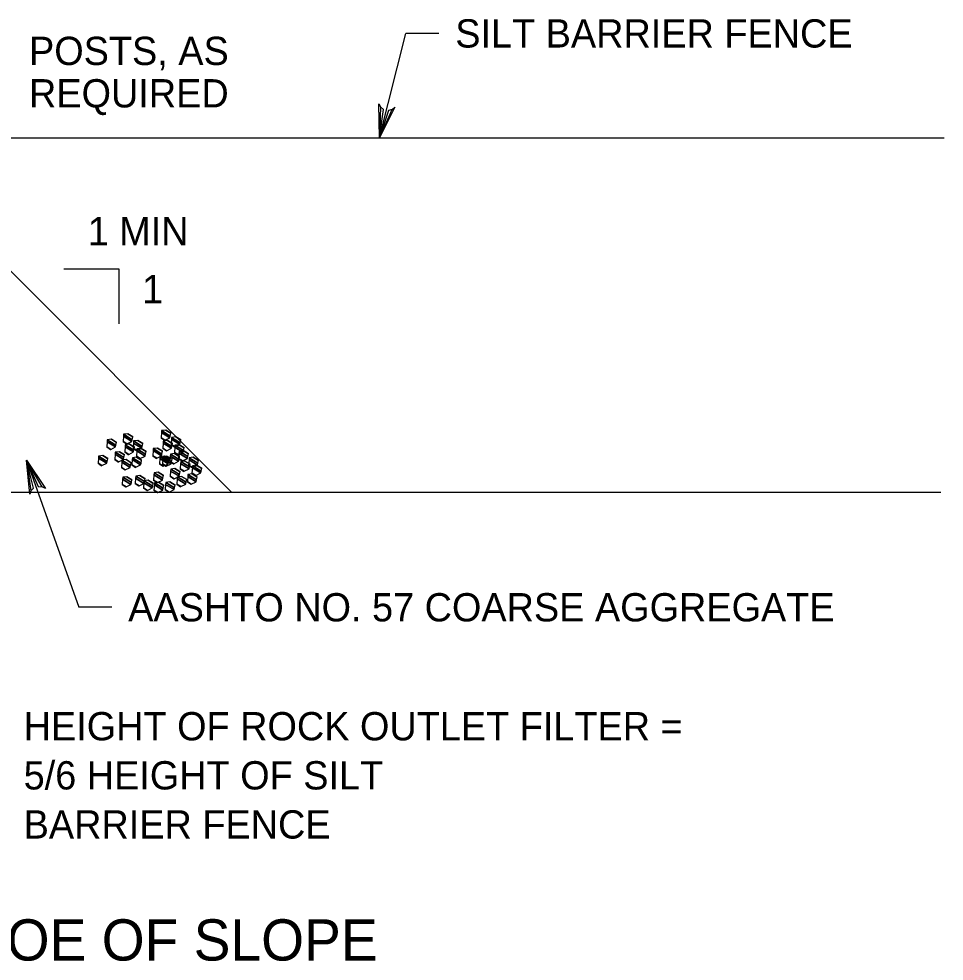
# Model space of a CAD drawing. Extents: x 636462 to 639049, y 299944 to 300538.
# Drawn here: x 637772.2 to 637870.3, y 300114 to 300213.9 of the extents above; entities that cross this region are included whole.
import ezdxf

# ---------------------------------------------------------------- set-up
doc = ezdxf.new("R2010")
doc.units = 0
doc.layers.add('Default', color=7, linetype='Continuous')

msp = doc.modelspace()

# ---------------------------------------------------------------- linework, layer by layer
at = {"layer": 'Default'}
for p, q in [((637810.476, 300201.292), (637813.243, 300212.352)), ((637816.741, 300212.352), (637813.243, 300212.352)), ((637761.425, 300201.292), (637870.293, 300201.292)), ((637794.794, 300163.723), (637763.334, 300195.182)), ((637773.044, 300167.11), (637778.583, 300151.525)), ((637719.268, 300163.723), (637869.927, 300163.723)), ((637782.081, 300151.525), (637778.583, 300151.525))]:
    msp.add_line(p, q, dxfattribs=at)
for points in [[(637811.811, 300204.304), (637812.088, 300204.517), (637810.476, 300201.292), (637811.811, 300204.304), (637811.404, 300204.195), (637810.476, 300201.292), (637810.892, 300204.304), (637810.566, 300204.565), (637810.476, 300201.292), (637810.381, 300204.896), (637810.566, 300204.565)], [(637777.012, 300187.412), (637782.853, 300187.412), (637782.853, 300181.575)], [(637773.525, 300163.851), (637773.405, 300163.523), (637773.044, 300167.11), (637773.525, 300163.851), (637773.811, 300164.161), (637773.044, 300167.11), (637774.302, 300164.342), (637774.717, 300164.296), (637773.044, 300167.11), (637775.051, 300164.115), (637774.717, 300164.296)]]:
    msp.add_lwpolyline(points, dxfattribs=at)
for points in [[(637787.369, 300170.247), (637788.288, 300169.677), (637788.352, 300169.966), (637787.81, 300170.302)], [(637787.81, 300170.302), (637788.352, 300169.966), (637788.354, 300169.974), (637788.354, 300169.974)], [(637781.603, 300169.07), (637782.491, 300168.52), (637782.537, 300168.718), (637781.619, 300169.286)], [(637781.619, 300169.286), (637782.537, 300168.718), (637782.602, 300168.997), (637782.056, 300169.335)], [(637782.056, 300169.335), (637782.602, 300168.997), (637782.604, 300169.007), (637782.604, 300169.007)], [(637783.284, 300169.092), (637783.703, 300168.832), (637784.22, 300169.092), (637783.325, 300169.647)], [(637783.325, 300169.647), (637784.22, 300169.092), (637784.263, 300169.285), (637783.34, 300169.857)], [(637783.34, 300169.857), (637784.263, 300169.285), (637784.327, 300169.575), (637783.781, 300169.913)], [(637783.781, 300169.913), (637784.327, 300169.575), (637784.329, 300169.586), (637784.329, 300169.586)], [(637787.313, 300169.481), (637787.727, 300169.224), (637788.245, 300169.481), (637787.353, 300170.033)], [(637787.699, 300169.21), (637787.699, 300169.21), (637787.727, 300169.224), (637787.313, 300169.481)], [(637787.353, 300170.033), (637788.245, 300169.481), (637788.288, 300169.677), (637787.369, 300170.247)], [(637788.378, 300168.773), (637788.795, 300168.515), (637789.309, 300168.773), (637788.416, 300169.326)], [(637788.416, 300169.326), (637789.309, 300168.773), (637789.352, 300168.966), (637788.431, 300169.537)], [(637788.431, 300169.537), (637789.352, 300168.966), (637789.417, 300169.25), (637788.866, 300169.592)], [(637788.866, 300169.592), (637789.417, 300169.25), (637789.42, 300169.264), (637789.42, 300169.264)], [(637781.563, 300168.52), (637781.981, 300168.26), (637782.491, 300168.52), (637781.603, 300169.07)], [(637781.947, 300168.243), (637781.947, 300168.243), (637781.981, 300168.26), (637781.563, 300168.52)], [(637783.67, 300168.815), (637783.67, 300168.815), (637783.703, 300168.832), (637783.284, 300169.092)], [(637783.466, 300167.988), (637783.884, 300167.729), (637784.398, 300167.988), (637783.502, 300168.543)], [(637783.502, 300168.543), (637784.398, 300167.988), (637784.441, 300168.179), (637783.516, 300168.753)], [(637783.516, 300168.753), (637784.441, 300168.179), (637784.505, 300168.469), (637783.957, 300168.809)], [(637783.957, 300168.809), (637784.505, 300168.469), (637784.507, 300168.48), (637784.507, 300168.48)], [(637784.35, 300168.384), (637784.765, 300168.127), (637785.28, 300168.384), (637784.39, 300168.936)], [(637784.734, 300168.111), (637784.734, 300168.111), (637784.765, 300168.127), (637784.35, 300168.384)], [(637784.39, 300168.936), (637785.28, 300168.384), (637785.324, 300168.582), (637784.406, 300169.151)], [(637784.406, 300169.151), (637785.324, 300168.582), (637785.389, 300168.872), (637784.845, 300169.21)], [(637784.742, 300168.094), (637785.634, 300167.541), (637785.678, 300167.741), (637784.758, 300168.312)], [(637784.758, 300168.312), (637785.678, 300167.741), (637785.741, 300168.03), (637785.199, 300168.366)], [(637784.845, 300169.21), (637785.389, 300168.872), (637785.391, 300168.88), (637785.391, 300168.88)], [(637785.199, 300168.366), (637785.741, 300168.03), (637785.743, 300168.039), (637785.743, 300168.039)], [(637786.469, 300168.13), (637787.361, 300167.577), (637787.405, 300167.771), (637786.483, 300168.342)], [(637786.483, 300168.342), (637787.405, 300167.771), (637787.469, 300168.058), (637786.92, 300168.399)], [(637786.92, 300168.399), (637787.469, 300168.058), (637787.472, 300168.071), (637787.472, 300168.071)], [(637787.49, 300168.374), (637787.903, 300168.118), (637788.423, 300168.374), (637787.53, 300168.928)], [(637787.873, 300168.103), (637787.873, 300168.103), (637787.903, 300168.118), (637787.49, 300168.374)], [(637787.53, 300168.928), (637788.423, 300168.374), (637788.466, 300168.57), (637787.545, 300169.141)], [(637787.545, 300169.141), (637788.466, 300168.57), (637788.53, 300168.858), (637787.986, 300169.195)], [(637787.986, 300169.195), (637788.53, 300168.858), (637788.532, 300168.87), (637788.532, 300168.87)], [(637788.757, 300168.496), (637788.757, 300168.496), (637788.795, 300168.515), (637788.378, 300168.773)], [(637788.73, 300167.935), (637789.152, 300167.674), (637789.661, 300167.935), (637788.771, 300168.487)], [(637788.771, 300168.487), (637789.661, 300167.935), (637789.705, 300168.131), (637788.787, 300168.7)], [(637788.787, 300168.7), (637789.705, 300168.131), (637789.77, 300168.414), (637789.224, 300168.753)], [(637789.224, 300168.753), (637789.77, 300168.414), (637789.772, 300168.423), (637789.772, 300168.423)], [(637780.634, 300166.793), (637781.05, 300166.535), (637781.563, 300166.793), (637780.674, 300167.344)], [(637780.674, 300167.344), (637781.563, 300166.793), (637781.608, 300166.99), (637780.689, 300167.559)], [(637780.689, 300167.559), (637781.608, 300166.99), (637781.673, 300167.274), (637781.126, 300167.614)], [(637781.126, 300167.614), (637781.673, 300167.274), (637781.676, 300167.286), (637781.676, 300167.286)], [(637782.404, 300167.189), (637782.818, 300166.933), (637783.332, 300167.189), (637782.443, 300167.741)], [(637782.443, 300167.741), (637783.332, 300167.189), (637783.377, 300167.39), (637782.459, 300167.96)], [(637782.459, 300167.96), (637783.377, 300167.39), (637783.441, 300167.676), (637782.895, 300168.014)], [(637782.895, 300168.014), (637783.441, 300167.676), (637783.444, 300167.687), (637783.444, 300167.687)], [(637783.844, 300167.709), (637783.844, 300167.709), (637783.884, 300167.729), (637783.466, 300167.988)], [(637784.254, 300167.173), (637785.15, 300166.617), (637785.193, 300166.808), (637784.269, 300167.381)], [(637784.269, 300167.381), (637785.193, 300166.808), (637785.257, 300167.1), (637784.712, 300167.438)], [(637784.701, 300167.541), (637785.116, 300167.284), (637785.634, 300167.541), (637784.742, 300168.094)], [(637785.088, 300167.27), (637785.088, 300167.27), (637785.116, 300167.284), (637784.701, 300167.541)], [(637784.712, 300167.438), (637785.257, 300167.1), (637785.26, 300167.11), (637785.26, 300167.11)], [(637786.433, 300167.577), (637786.848, 300167.32), (637787.361, 300167.577), (637786.469, 300168.13)], [(637786.813, 300167.302), (637786.813, 300167.302), (637786.848, 300167.32), (637786.433, 300167.577)], [(637787.137, 300166.738), (637787.55, 300166.482), (637788.067, 300166.738), (637787.177, 300167.29)], [(637787.177, 300167.29), (637788.067, 300166.738), (637788.112, 300166.933), (637787.193, 300167.503)], [(637787.193, 300167.503), (637788.112, 300166.933), (637788.178, 300167.222), (637787.634, 300167.559)], [(637787.448, 300166.738), (637787.86, 300166.483), (637788.378, 300166.738), (637787.487, 300167.291)], [(637787.487, 300167.291), (637788.378, 300166.738), (637788.422, 300166.932), (637787.503, 300167.503)], [(637787.503, 300167.503), (637788.422, 300166.932), (637788.487, 300167.219), (637787.937, 300167.559)], [(637787.634, 300167.559), (637788.178, 300167.222), (637788.18, 300167.23), (637788.18, 300167.23)], [(637787.937, 300167.559), (637788.487, 300167.219), (637788.49, 300167.23), (637788.49, 300167.23)], [(637788.243, 300167.005), (637788.661, 300166.746), (637789.175, 300167.005), (637788.282, 300167.559)], [(637788.282, 300167.559), (637789.175, 300167.005), (637789.219, 300167.199), (637788.297, 300167.77)], [(637788.297, 300167.77), (637789.219, 300167.199), (637789.283, 300167.487), (637788.738, 300167.824)], [(637789.117, 300167.656), (637789.117, 300167.656), (637789.152, 300167.674), (637788.73, 300167.935)], [(637788.738, 300167.824), (637789.283, 300167.487), (637789.284, 300167.493), (637789.284, 300167.493)], [(637789.171, 300167.311), (637789.587, 300167.053), (637790.104, 300167.311), (637789.212, 300167.863)], [(637789.555, 300167.037), (637789.555, 300167.037), (637789.587, 300167.053), (637789.171, 300167.311)], [(637789.212, 300167.863), (637790.104, 300167.311), (637790.147, 300167.509), (637789.228, 300168.079)], [(637789.228, 300168.079), (637790.147, 300167.509), (637790.211, 300167.796), (637789.667, 300168.134)], [(637789.667, 300168.134), (637790.211, 300167.796), (637790.213, 300167.806), (637790.213, 300167.806)], [(637790.276, 300167.156), (637791.165, 300166.605), (637791.211, 300166.805), (637790.292, 300167.375)], [(637790.292, 300167.375), (637791.211, 300166.805), (637791.276, 300167.088), (637790.724, 300167.43)], [(637790.724, 300167.43), (637791.276, 300167.088), (637791.279, 300167.098), (637791.279, 300167.098)], [(637781.017, 300166.518), (637781.017, 300166.518), (637781.05, 300166.535), (637780.634, 300166.793)], [(637782.788, 300166.918), (637782.788, 300166.918), (637782.818, 300166.933), (637782.404, 300167.189)], [(637783.11, 300166.35), (637783.524, 300166.093), (637784.044, 300166.35), (637783.149, 300166.905)], [(637783.492, 300166.077), (637783.492, 300166.077), (637783.524, 300166.093), (637783.11, 300166.35)], [(637783.149, 300166.905), (637784.044, 300166.35), (637784.086, 300166.545), (637783.164, 300167.116)], [(637783.164, 300167.116), (637784.086, 300166.545), (637784.149, 300166.836), (637783.605, 300167.173)], [(637783.605, 300167.173), (637784.149, 300166.836), (637784.151, 300166.845), (637784.151, 300166.845)], [(637784.214, 300166.617), (637784.632, 300166.358), (637785.15, 300166.617), (637784.254, 300167.173)], [(637784.596, 300166.34), (637784.596, 300166.34), (637784.632, 300166.358), (637784.214, 300166.617)], [(637787.521, 300166.467), (637787.521, 300166.467), (637787.55, 300166.482), (637787.137, 300166.738)], [(637787.828, 300166.467), (637787.828, 300166.467), (637787.86, 300166.483), (637787.448, 300166.738)], [(637788.625, 300166.728), (637788.625, 300166.728), (637788.661, 300166.746), (637788.243, 300167.005)], [(637789.347, 300166.204), (637789.762, 300165.947), (637790.28, 300166.204), (637789.386, 300166.758)], [(637789.386, 300166.758), (637790.28, 300166.204), (637790.323, 300166.403), (637789.402, 300166.975)], [(637789.402, 300166.975), (637790.323, 300166.403), (637790.387, 300166.693), (637789.845, 300167.029)], [(637789.845, 300167.029), (637790.387, 300166.693), (637790.389, 300166.702), (637790.389, 300166.702)], [(637790.237, 300166.605), (637790.648, 300166.35), (637791.165, 300166.605), (637790.276, 300167.156)], [(637790.615, 300166.334), (637790.615, 300166.334), (637790.648, 300166.35), (637790.237, 300166.605)], [(637790.589, 300165.765), (637791.006, 300165.507), (637791.519, 300165.765), (637790.63, 300166.317)], [(637790.63, 300166.317), (637791.519, 300165.765), (637791.564, 300165.963), (637790.646, 300166.532)], [(637790.646, 300166.532), (637791.564, 300165.963), (637791.628, 300166.249), (637791.08, 300166.588)], [(637791.08, 300166.588), (637791.628, 300166.249), (637791.631, 300166.261), (637791.631, 300166.261)], [(637783.229, 300165.102), (637784.123, 300164.548), (637784.166, 300164.745), (637783.245, 300165.316)], [(637783.245, 300165.316), (637784.166, 300164.745), (637784.228, 300165.027), (637783.68, 300165.367)], [(637783.68, 300165.367), (637784.228, 300165.027), (637784.23, 300165.039), (637784.23, 300165.039)], [(637784.61, 300165.212), (637785.502, 300164.659), (637785.547, 300164.856), (637784.625, 300165.428)], [(637784.625, 300165.428), (637785.547, 300164.856), (637785.613, 300165.144), (637785.064, 300165.484)], [(637785.064, 300165.484), (637785.613, 300165.144), (637785.616, 300165.157), (637785.616, 300165.157)], [(637786.52, 300165.011), (637786.933, 300164.755), (637787.448, 300165.011), (637786.557, 300165.563)], [(637786.557, 300165.563), (637787.448, 300165.011), (637787.493, 300165.209), (637786.572, 300165.779)], [(637786.572, 300165.779), (637787.493, 300165.209), (637787.558, 300165.496), (637787.009, 300165.836)], [(637787.009, 300165.836), (637787.558, 300165.496), (637787.561, 300165.508), (637787.561, 300165.508)], [(637788.291, 300165.411), (637788.705, 300165.155), (637789.218, 300165.411), (637788.328, 300165.963)], [(637788.672, 300165.138), (637788.672, 300165.138), (637788.705, 300165.155), (637788.291, 300165.411)], [(637788.328, 300165.963), (637789.218, 300165.411), (637789.264, 300165.609), (637788.342, 300166.18)], [(637788.342, 300166.18), (637789.264, 300165.609), (637789.329, 300165.889), (637788.779, 300166.231)], [(637788.779, 300166.231), (637789.329, 300165.889), (637789.333, 300165.907), (637789.333, 300165.907)], [(637789.035, 300165.126), (637789.928, 300164.572), (637789.971, 300164.77), (637789.05, 300165.341)], [(637789.05, 300165.341), (637789.971, 300164.77), (637790.035, 300165.061), (637789.493, 300165.397)], [(637789.733, 300165.933), (637789.733, 300165.933), (637789.762, 300165.947), (637789.347, 300166.204)], [(637789.493, 300165.397), (637790.035, 300165.061), (637790.037, 300165.07), (637790.037, 300165.07)], [(637790.102, 300164.835), (637790.515, 300164.579), (637791.032, 300164.835), (637790.142, 300165.387)], [(637790.142, 300165.387), (637791.032, 300164.835), (637791.076, 300165.036), (637790.158, 300165.606)], [(637790.158, 300165.606), (637791.076, 300165.036), (637791.14, 300165.324), (637790.597, 300165.66)], [(637790.973, 300165.49), (637790.973, 300165.49), (637791.006, 300165.507), (637790.589, 300165.765)], [(637790.597, 300165.66), (637791.14, 300165.324), (637791.141, 300165.331), (637791.141, 300165.331)], [(637783.189, 300164.548), (637783.604, 300164.29), (637784.123, 300164.548), (637783.229, 300165.102)], [(637783.573, 300164.275), (637783.573, 300164.275), (637783.604, 300164.29), (637783.189, 300164.548)], [(637784.572, 300164.659), (637784.987, 300164.402), (637785.502, 300164.659), (637784.61, 300165.212)], [(637784.956, 300164.386), (637784.956, 300164.386), (637784.987, 300164.402), (637784.572, 300164.659)], [(637785.456, 300164.176), (637785.875, 300163.916), (637786.386, 300164.176), (637785.497, 300164.727)], [(637785.497, 300164.727), (637786.386, 300164.176), (637786.43, 300164.371), (637785.513, 300164.94)], [(637785.513, 300164.94), (637786.43, 300164.371), (637786.494, 300164.66), (637785.951, 300164.997)], [(637785.951, 300164.997), (637786.494, 300164.66), (637786.495, 300164.665), (637786.495, 300164.665)], [(637786.9, 300164.738), (637786.9, 300164.738), (637786.933, 300164.755), (637786.52, 300165.011)], [(637786.56, 300163.955), (637786.977, 300163.697), (637787.493, 300163.955), (637786.601, 300164.508)], [(637786.601, 300164.508), (637787.493, 300163.955), (637787.536, 300164.15), (637786.617, 300164.72)], [(637786.617, 300164.72), (637787.536, 300164.15), (637787.599, 300164.436), (637787.058, 300164.772)], [(637787.058, 300164.772), (637787.599, 300164.436), (637787.602, 300164.447), (637787.602, 300164.447)], [(637787.755, 300163.994), (637788.168, 300163.738), (637788.692, 300163.994), (637787.795, 300164.55)], [(637787.795, 300164.55), (637788.692, 300163.994), (637788.735, 300164.189), (637787.81, 300164.762)], [(637787.81, 300164.762), (637788.735, 300164.189), (637788.798, 300164.478), (637788.249, 300164.819)], [(637788.249, 300164.819), (637788.798, 300164.478), (637788.801, 300164.491), (637788.801, 300164.491)], [(637788.995, 300164.572), (637789.41, 300164.315), (637789.928, 300164.572), (637789.035, 300165.126)], [(637789.377, 300164.299), (637789.377, 300164.299), (637789.41, 300164.315), (637788.995, 300164.572)], [(637790.486, 300164.564), (637790.486, 300164.564), (637790.515, 300164.579), (637790.102, 300164.835)], [(637785.84, 300163.899), (637785.84, 300163.899), (637785.875, 300163.916), (637785.456, 300164.176)], [(637786.944, 300163.68), (637786.944, 300163.68), (637786.977, 300163.697), (637786.56, 300163.955)], [(637788.138, 300163.723), (637788.138, 300163.723), (637788.168, 300163.738), (637787.755, 300163.994)]]:
    msp.add_lwpolyline(points, close=True, dxfattribs=at)

# ---------------------------------------------------------------- texts
for s, height, p in [('SILT BARRIER FENCE', 2.99804, (637818.489, 300210.853)), ('POSTS, AS', 2.998, (637773.322, 300209.001)), ('REQUIRED', 2.998, (637773.322, 300204.504)), ('1 MIN', 2.998, (637779.536, 300189.885)), ('1', 2.998, (637785.298, 300183.751)), ('AASHTO NO. 57 COARSE AGGREGATE', 2.99804, (637783.83, 300150.026)), ('HEIGHT OF ROCK OUTLET FILTER =', 2.99804, (637772.753, 300137.419)), ('5/6 HEIGHT OF SILT', 2.99804, (637772.753, 300132.214)), ('BARRIER FENCE', 2.99804, (637772.753, 300127.008)), ('FILTER AT TOE OF SLOPE', 4.37213, (637736.521, 300114.077))]:
    msp.add_text(s, height=height, dxfattribs=at).set_placement(p)

doc.saveas('drawing.dxf')
